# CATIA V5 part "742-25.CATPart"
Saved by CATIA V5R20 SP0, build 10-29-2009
Part number: 742-25
Bounding box of the stored display mesh (mm): x -24 to 25, y -23.94 to 23.94, z -23 to 56
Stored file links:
  C:\Users\Utente\Desktop\IO LAVORO\3D X SITO CF\X SITO\742\742-25.CATPart
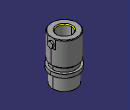
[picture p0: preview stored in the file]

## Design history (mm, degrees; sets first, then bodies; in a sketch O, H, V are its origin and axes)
Set1
  DatumSurface1 to DatumSurface38 "742-25"
Body1 (main body)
